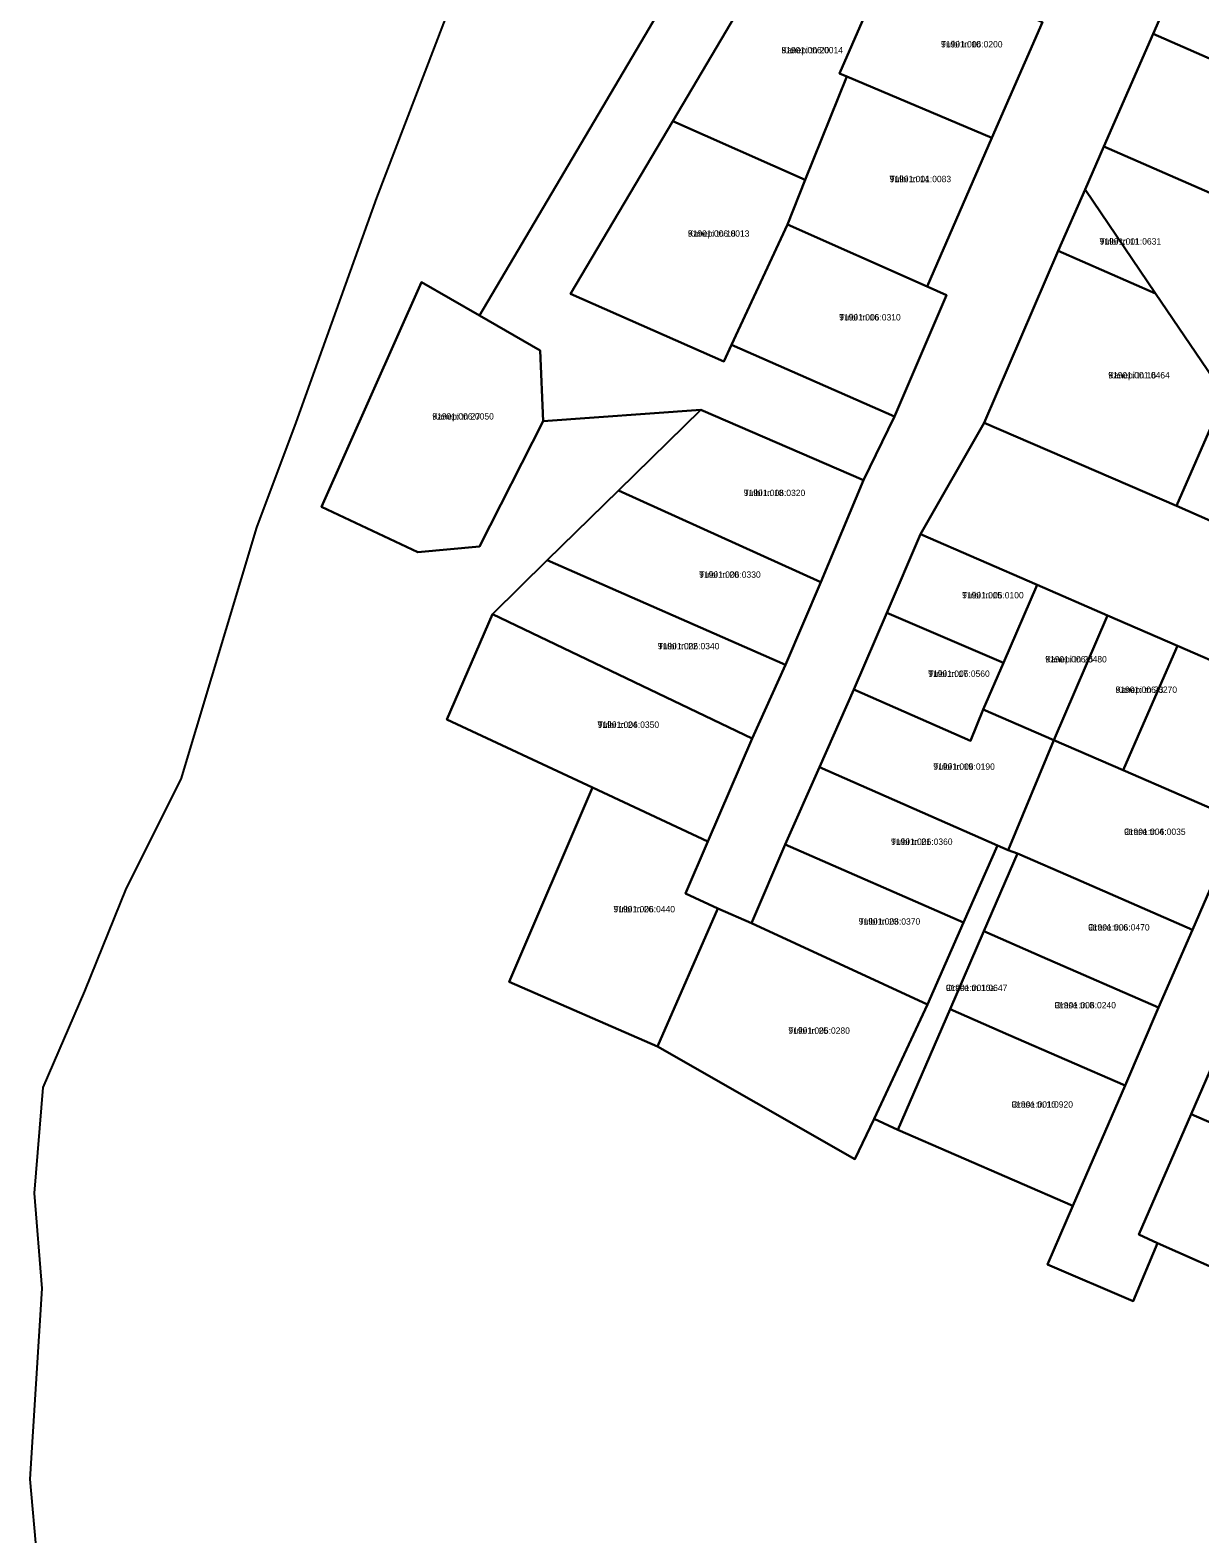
# Model space of a CAD drawing. Extents: x 675810 to 681273, y 6411190 to 6417565.
# Drawn here: x 675810.1 to 676085.9, y 6416424.5 to 6416779.2 of the extents above; entities that cross this region are included whole.
import ezdxf

# ---------------------------------------------------------------- set-up
doc = ezdxf.new("R2010")
doc.units = 0
for name, color, linetype in [('L_AADRESS', 7, 'Continuous'), ('PIIR', 7, 'Continuous'), ('TUNNUS', 7, 'Continuous')]:
    doc.layers.add(name, color=color, linetype=linetype)

msp = doc.modelspace()

# ---------------------------------------------------------------- linework, layer by layer
at = {"layer": 'PIIR'}
for points in [[(675811.82, 6416418.84), (675810.13, 6416437.41), (675812.94, 6416482.41), (675811.2, 6416504.87), (675813.18, 6416529.81), (675823.02, 6416552.54), (675832.86, 6416576.78), (675845.73, 6416602.53), (675863.59, 6416661.89), (675872.86, 6416686.64), (675891.91, 6416739.64), (675916.87, 6416804.9), (675944.33, 6416874.77), (675952.2, 6416886.46), (675977.73, 6416917.36), (676028.49, 6416973.93), (676183.01, 6417122.5)], [(675975.97, 6416813.41), (675916.07, 6416711.86), (675902.44, 6416719.73), (675878.8, 6416666.72), (675901.53, 6416656.09), (675916.07, 6416657.42), (675931.12, 6416686.94), (675968.22, 6416689.6), (675948.85, 6416670.58), (675932.06, 6416654.18), (675919.13, 6416641.42), (675908.39, 6416616.6), (675942.72, 6416600.53), (675923.1, 6416554.71), (675958.04, 6416539.48), (676004.54, 6416512.89), (676009.12, 6416522.4), (676014.67, 6416519.81), (676055.94, 6416501.84), (676049.98, 6416488.07), (676070.21, 6416479.42), (676075.95, 6416493.1), (676115.68, 6416475.47)], [(676084.89, 6416801.21), (676074.89, 6416778.3), (676063.28, 6416751.72), (676058.88, 6416741.63), (676052.52, 6416727.12), (676035.06, 6416686.57), (676020.07, 6416660.3), (676012.1, 6416641.77), (676004.3, 6416623.65), (675996.2, 6416605.34), (675988.18, 6416587.07), (675980.18, 6416568.58), (675972.24, 6416572.02), (675964.68, 6416575.51), (675969.89, 6416587.81), (675980.4, 6416612.13), (675988.24, 6416629.47), (675996.55, 6416648.98), (676006.62, 6416673.01), (676013.89, 6416688.08), (676026.17, 6416716.71), (676021.63, 6416718.76), (676036.86, 6416753.78), (676048.79, 6416781.11)], [(676108.12, 6416622.01), (676080.6, 6416633.98), (676064.1, 6416641.16), (676047.57, 6416648.32), (676020.07, 6416660.3), (676035.06, 6416686.57), (676080.36, 6416666.96), (676126.49, 6416646.66)]]:
    msp.add_lwpolyline(points, dxfattribs=at)
for points in [[(676013.89, 6416688.08), (676006.62, 6416673.01), (675968.22, 6416689.6), (675931.12, 6416686.94), (675930.36, 6416703.63), (675916.07, 6416711.86), (675975.97, 6416813.41), (676006.09, 6416883.47), (676020.68, 6416876.88), (676009.6, 6416851.76), (675999.55, 6416828.01), (675990.25, 6416806.12), (675961.62, 6416757.73), (675937.52, 6416716.97), (675973.67, 6416701.07), (675975.5, 6416704.99)], [(675990.25, 6416806.12), (676012.93, 6416796.44), (676000.92, 6416768.95), (676002.67, 6416768.25), (675992.89, 6416743.89), (675961.62, 6416757.73)], [(676128.92, 6416781.96), (676118.85, 6416759.06), (676074.89, 6416778.3), (676084.89, 6416801.21)], [(676036.86, 6416753.78), (676002.67, 6416768.25), (676000.92, 6416768.95), (676012.93, 6416796.44), (676048.79, 6416781.11)], [(676074.89, 6416778.3), (676118.85, 6416759.06), (676124.9, 6416756.46), (676113.24, 6416729.91), (676063.28, 6416751.72)], [(675992.89, 6416743.89), (676002.67, 6416768.25), (676036.86, 6416753.78), (676021.63, 6416718.76), (675988.66, 6416733.34)], [(675961.62, 6416757.73), (675992.89, 6416743.89), (675988.66, 6416733.34), (675975.5, 6416704.99), (675973.67, 6416701.07), (675937.52, 6416716.97)], [(676063.28, 6416751.72), (676113.24, 6416729.91), (676130.99, 6416722.19), (676126.59, 6416712.06), (676118.62, 6416693.7), (676114.1, 6416683.32), (676091.78, 6416693.01), (676075.42, 6416717.09), (676058.88, 6416741.63)], [(676058.88, 6416741.63), (676075.42, 6416717.09), (676052.52, 6416727.12)], [(676013.89, 6416688.08), (675975.5, 6416704.99), (675988.66, 6416733.34), (676021.63, 6416718.76), (676026.17, 6416716.71)], [(676035.06, 6416686.57), (676052.52, 6416727.12), (676075.42, 6416717.09), (676091.78, 6416693.01), (676090.23, 6416689.47), (676080.36, 6416666.96)], [(675916.07, 6416657.42), (675901.53, 6416656.09), (675878.8, 6416666.72), (675902.44, 6416719.73), (675916.07, 6416711.86), (675930.36, 6416703.63), (675931.12, 6416686.94)], [(675996.55, 6416648.98), (675948.85, 6416670.58), (675968.22, 6416689.6), (676006.62, 6416673.01)], [(676091.78, 6416693.01), (676114.1, 6416683.32), (676110.64, 6416675.41), (676134.51, 6416664.99), (676126.49, 6416646.66), (676080.36, 6416666.96), (676090.23, 6416689.47)], [(675932.06, 6416654.18), (675948.85, 6416670.58), (675996.55, 6416648.98), (675988.24, 6416629.47)], [(676047.57, 6416648.32), (676039.59, 6416629.99), (676012.1, 6416641.77), (676020.07, 6416660.3)], [(675919.13, 6416641.42), (675932.06, 6416654.18), (675988.24, 6416629.47), (675980.4, 6416612.13)], [(676064.1, 6416641.16), (676051.45, 6416611.74), (676034.83, 6416618.95), (676039.59, 6416629.99), (676047.57, 6416648.32)], [(675942.72, 6416600.53), (675908.39, 6416616.6), (675919.13, 6416641.42), (675980.4, 6416612.13), (675969.89, 6416587.81)], [(676012.1, 6416641.77), (676039.59, 6416629.99), (676034.83, 6416618.95), (676031.86, 6416611.52), (676004.3, 6416623.65)], [(676080.6, 6416633.98), (676072.63, 6416615.65), (676067.83, 6416604.64), (676051.45, 6416611.74), (676064.1, 6416641.16)], [(676080.6, 6416633.98), (676108.12, 6416622.01), (676095.35, 6416592.67), (676067.83, 6416604.64), (676072.63, 6416615.65)], [(676004.3, 6416623.65), (676031.86, 6416611.52), (676034.83, 6416618.95), (676051.45, 6416611.74), (676040.69, 6416585.8), (676038.23, 6416586.88), (675996.2, 6416605.34)], [(676108.12, 6416622.01), (676123.72, 6416615.22), (676115.74, 6416596.89), (676107.76, 6416578.54), (676096.26, 6416552.11), (676083.82, 6416523.52), (676071.48, 6416495.08), (676075.95, 6416493.1), (676070.21, 6416479.42), (676049.98, 6416488.07), (676055.94, 6416501.84), (676068.31, 6416530.27), (676076.19, 6416548.67), (676084.17, 6416567), (676095.35, 6416592.67)], [(676051.45, 6416611.74), (676067.83, 6416604.64), (676095.35, 6416592.67), (676084.17, 6416567), (676056.67, 6416578.98), (676042.92, 6416584.97), (676040.69, 6416585.8)], [(675988.18, 6416587.07), (675996.2, 6416605.34), (676038.23, 6416586.88), (676030.19, 6416568.7)], [(675958.04, 6416539.48), (675923.1, 6416554.71), (675942.72, 6416600.53), (675969.89, 6416587.81), (675964.68, 6416575.51), (675972.24, 6416572.02)], [(676021.67, 6416549.33), (675980.18, 6416568.58), (675988.18, 6416587.07), (676030.19, 6416568.7)], [(676027.04, 6416548.23), (676014.67, 6416519.81), (676009.12, 6416522.4), (676021.67, 6416549.33), (676030.19, 6416568.7), (676038.23, 6416586.88), (676040.69, 6416585.8), (676042.92, 6416584.97), (676034.94, 6416566.63)], [(676076.19, 6416548.67), (676048.69, 6416560.64), (676034.94, 6416566.63), (676042.92, 6416584.97), (676056.67, 6416578.98), (676084.17, 6416567)], [(675972.24, 6416572.02), (675980.18, 6416568.58), (676021.67, 6416549.33), (676009.12, 6416522.4), (676004.54, 6416512.89), (675958.04, 6416539.48)], [(676068.31, 6416530.27), (676040.79, 6416542.24), (676027.04, 6416548.23), (676034.94, 6416566.63), (676048.69, 6416560.64), (676076.19, 6416548.67)], [(676096.26, 6416552.11), (676116.89, 6416543.12), (676140.33, 6416532.92), (676136.14, 6416523.12), (676128.08, 6416504.36), (676111.32, 6416511.55), (676083.82, 6416523.52)], [(676055.94, 6416501.84), (676014.67, 6416519.81), (676027.04, 6416548.23), (676040.79, 6416542.24), (676068.31, 6416530.27)], [(676083.82, 6416523.52), (676111.32, 6416511.55), (676128.08, 6416504.36), (676125.94, 6416499.31), (676115.68, 6416475.47), (676075.95, 6416493.1), (676071.48, 6416495.08)]]:
    msp.add_lwpolyline(points, close=True, dxfattribs=at)

# ---------------------------------------------------------------- texts
at = {"layer": 'L_AADRESS'}
for s, p in [('Kanepi tn 20', (675987.27, 6416773.73)), ('Tulbi tn 10', (676024.89, 6416775.11)), ('Tulbi tn 14', (676012.76, 6416743.33)), ('Kanepi tn 18', (675965.21, 6416730.47)), ('Tulbi tn 11', (676062.27, 6416728.61)), ('Tulbi tn 16', (676000.88, 6416710.71)), ('Kanepi tn 16', (676064.31, 6416697.04)), ('Kanepi tn 27', (675904.96, 6416687.34)), ('Tulbi tn 18', (675978.38, 6416669.29)), ('Tulbi tn 20', (675967.87, 6416650.02)), ('Tulbi tn 15', (676029.87, 6416645.15)), ('Tulbi tn 22', (675958.14, 6416633.15)), ('Kanepi tn 25', (676049.46, 6416630.05)), ('Tulbi tn 17', (676021.87, 6416626.65)), ('Kanepi tn 23', (676066.03, 6416622.87)), ('Tulbi tn 24', (675943.92, 6416614.62)), ('Tulbi tn 19', (676023.07, 6416604.73)), ('Orase tn 4', (676068.04, 6416589.37)), ('Tulbi tn 21', (676013.1, 6416587.02)), ('Tulbi tn 26', (675947.67, 6416571.11)), ('Tulbi tn 23', (676005.48, 6416568.2)), ('Orase tn 6', (676059.56, 6416566.82)), ('Orase tn 10a', (676026.02, 6416552.55)), ('Orase tn 8', (676051.62, 6416548.45)), ('Tulbi tn 25', (675988.9, 6416542.46)), ('Orase tn 10', (676041.49, 6416525.04))]:
    msp.add_text(s, height=1.5, dxfattribs=at).set_placement(p)
at = {"layer": 'TUNNUS'}
for s, p in [('91901:006:0014', (675987.27, 6416773.73)), ('91901:006:0200', (676024.89, 6416775.11)), ('91901:001:0083', (676012.76, 6416743.33)), ('91901:006:0013', (675965.21, 6416730.47)), ('91901:001:0631', (676062.27, 6416728.61)), ('91901:006:0310', (676000.88, 6416710.71)), ('91901:001:0464', (676064.31, 6416697.04)), ('91901:006:0050', (675904.96, 6416687.34)), ('91901:006:0320', (675978.38, 6416669.29)), ('91901:006:0330', (675967.87, 6416650.02)), ('91901:006:0100', (676029.87, 6416645.15)), ('91901:006:0340', (675958.14, 6416633.15)), ('91901:006:0480', (676049.46, 6416630.05)), ('91901:006:0560', (676021.87, 6416626.65)), ('91901:006:0270', (676066.03, 6416622.87)), ('91901:006:0350', (675943.92, 6416614.62)), ('91901:006:0190', (676023.07, 6416604.73)), ('91901:006:0035', (676068.04, 6416589.37)), ('91901:006:0360', (676013.1, 6416587.02)), ('91901:006:0440', (675947.67, 6416571.11)), ('91901:006:0370', (676005.48, 6416568.2)), ('91901:006:0470', (676059.56, 6416566.82)), ('91901:001:0647', (676026.02, 6416552.55)), ('91901:006:0240', (676051.62, 6416548.45)), ('91901:006:0280', (675988.9, 6416542.46)), ('91901:001:0920', (676041.49, 6416525.04))]:
    msp.add_text(s, height=1.5, dxfattribs=at).set_placement(p)

doc.saveas('drawing.dxf')
